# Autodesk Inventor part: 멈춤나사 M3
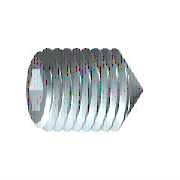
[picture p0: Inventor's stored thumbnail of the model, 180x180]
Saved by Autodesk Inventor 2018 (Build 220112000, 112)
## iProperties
IsCustomPart: 1
Created: 2012-02
Part Number: 멈춤나사 M3
Material: 강철, 연강
Description: 6각 소켓 머리 없는 멈춤 나사
Document SubType Name: Modeling
Standard: KS B 1028
Designer: test
Standards Organization: KS
Language: ko-KR
Size Designation: 원추점 M3x8
Categories: <MemberInstance><Categories><Category DisplayName="조임쇠" InternalName="e4da775c-781d-43d5-af7c-5136215cf5a6" Mnemonic="FSTN"><Category DisplayName="볼트" InternalN
Density: 1 g/cm^3
Appearance: 강철
Author: test
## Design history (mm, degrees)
sketch "스케치1"
  geometry: L1 (0, 0)-(5.5, 0); L2 (8, 0.866)-(8, 1.5); L3 (8, 1.5)-(0, 1.5); L4 (8, 0.866)-(6, 0.866); L5 (6, 0.866)-(5.5, 0); L6 (0, -0.3)-(0, 1.8) reference; L7 (0, 1.5)-(0, 0)
  constraints: 13 end point, 3 parallel, 1 collinear, 1 perpendicular, 1 point on line
  dimensions: "d0" = 2 distance of L2.start L4.end (= INTI); "d1" = 60 deg angle of L5 L1; "d2" = 3 diameter of L3 L1 (= NND); "d3" = 1.73205 diameter of L4 L1 (= 1.1547 x SW); "d5" = 8 distance from line of L2 L3.end (= NLG)
revolve "본체" sketch "스케치1" stored, may be unused: angle "d6" = 90 deg
sketch "스케치2"
  geometry: L1 (-0.433, 0.75)-(0.433, 0.75); L2 (0.433, 0.75)-(0.866, 0); L3 (0.866, 0)-(0.433, -0.75); L4 (0.433, -0.75)-(-0.433, -0.75); L5 (-0.433, -0.75)-(-0.866, 0); L6 (-0.866, 0)-(-0.433, 0.75); 3 further points
  constraints: 12 end point, 1 coincident, 1 horizontal, 13 other
extrude "슬롯" join sketch "스케치2" taper "d7" = 0 deg; stored distance "d21" = 10
workaxis "Work Axis1"
workplane "Work Plane1"
sketch "스케치4"
  geometry: L1 (0, 0.15)-(-1.35, 1.5) reference; L2 (0, -0.15)-(-1.35, -1.5) reference; L3 (-1.35, -1.5)-(0.15, 0); L4 (-1.35, 1.5)-(0.15, 0); 2 further points
  constraints: 4 end point, 1 coincident, 1 collinear, 1 horizontal alignment
body "Solid1"
feature "스레드" dims "d12" = 8 (= NLG), "d13" = 0
chamfer "모따기1" distance "d8" = 1.35 (computed from NND, SPD, FAWI); stored, may be unused: angle "d9" = 45 deg (= FAWI), second distance "d34" = 1.35 (computed from NND, SPD, FAWI)
chamfer "모따기2" distance "d10" = 0.30673 (= -0.5 x GD1 + 0.5 x NND); stored, may be unused: angle "d11" = 45 deg (= FAWI), second distance "d35" = 0.30673 (= -0.5 x GD1 + 0.5 x NND)
other parameters: "NND" = 3 [user parameter; used in 5 equation terms], "NLG" = 8 [user parameter; used in 2 equation terms], "INTI" = 2 [user parameter; used in 1 equation term], "FAWI" = 45 deg [user parameter; used in 4 equation terms], "SW" = 1.5 [user parameter; used in 2 equation terms], "GD1" = 2.38655 (= THREADDIA - 1.2269 x PTC) [user parameter; used in 2 equation terms], "d4" = 0, "FAWI1" = 45 deg [user parameter], "SPD" = 0.3 [user parameter; used in 2 equation terms], "d36" = 0, "d37" = 0, "GUL" = 0.30673 (= 0.61345 x PTC) [user parameter], "TOA" = 30 deg [user parameter], "THREADDIA" = 3 [user parameter; used in 1 equation term], "PTC" = 0.5 [user parameter; used in 4 equation terms], "GAL" = 0.30673 (= 0.61345 x PTC) [user parameter], "E0" = 1.7325 (= 1.155 x SW) [user parameter]
